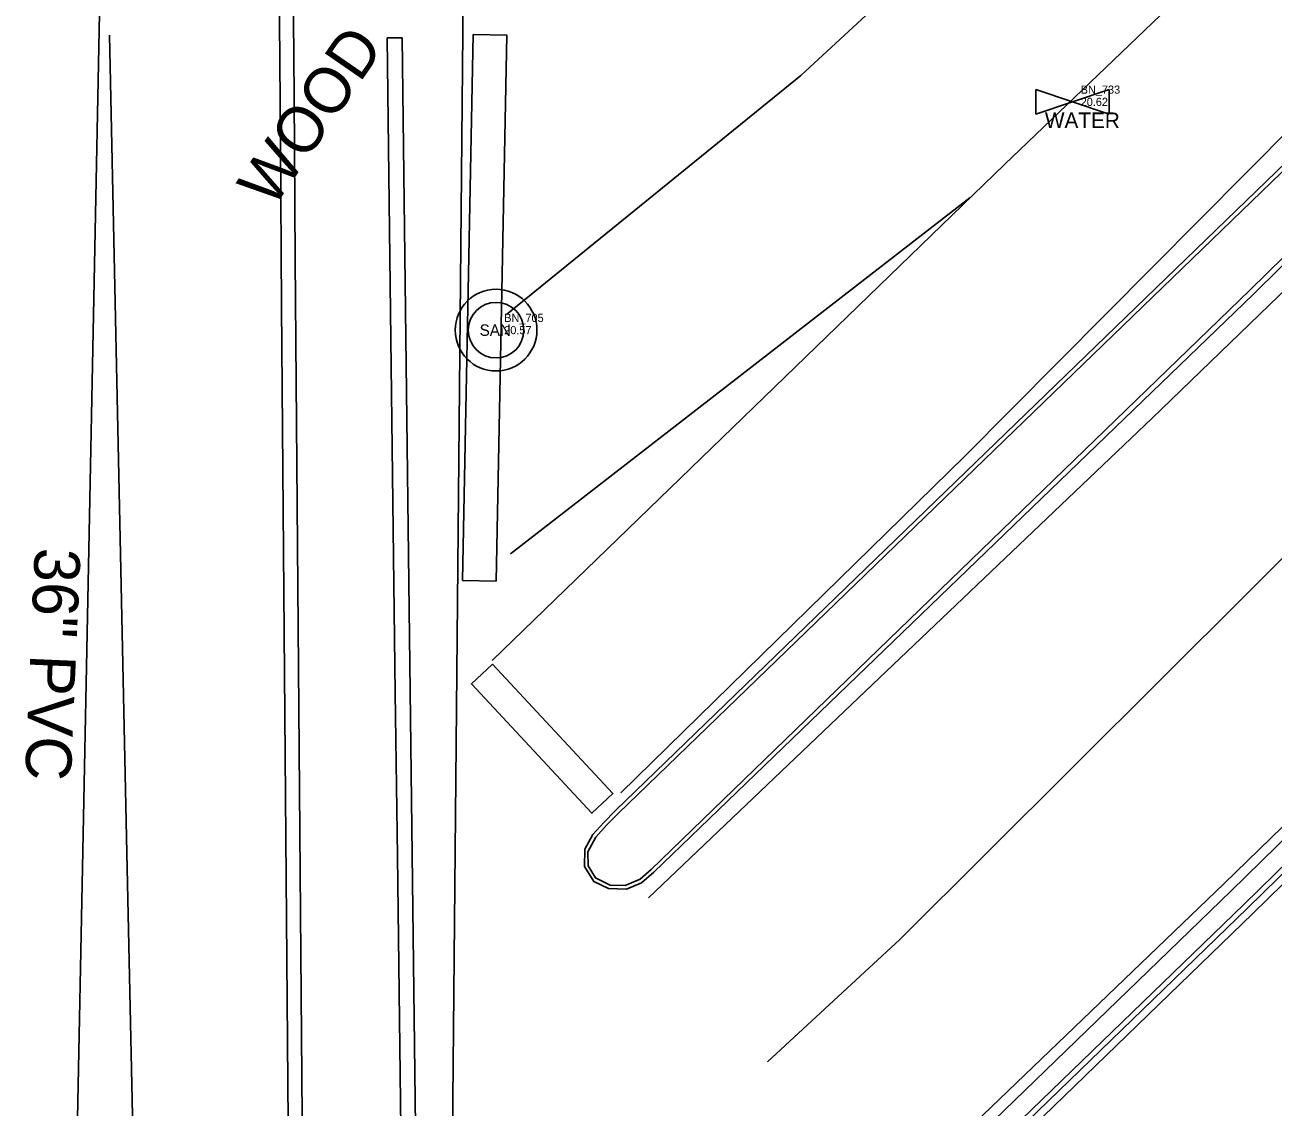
# Model space of a CAD drawing. Extents: x 509744 to 512285, y 1314862 to 1316822.
# Drawn here: x 510499.4 to 510575.8, y 1316002.7 to 1316068.9 of the extents above; entities that cross this region are included whole.
import ezdxf

# ---------------------------------------------------------------- set-up
doc = ezdxf.new("R2010")
doc.units = 0
for name, color, linetype in [('CGBack_ep', 7, 'Continuous'), ('CGep_ep', 7, 'Continuous'), ('CGFace_ep', 7, 'Continuous'), ('ElecAer_ep', 7, 'Continuous'), ('LaneLine_ep', 7, 'Continuous'), ('ManholeSS_ep', 7, 'Continuous'), ('NonPlottingEle_dp', 7, 'Continuous'), ('PavtAsphalt_ep', 7, 'Continuous'), ('PavtBreak_ep', 7, 'Continuous'), ('PipeCulvert_ep', 7, 'Continuous'), ('PMRK_ep', 7, 'Continuous'), ('TextElevLabel', 7, 'Continuous'), ('TextPtLabel', 7, 'Continuous'), ('TextTopoLabel_ep', 7, 'Continuous'), ('ValveWater_ep', 7, 'Continuous')]:
    doc.layers.add(name, color=color, linetype=linetype)

msp = doc.modelspace()

# ---------------------------------------------------------------- linework, layer by layer
at = {"layer": 'CGBack_ep'}
msp.add_lwpolyline([(510906.619, 1316389.372), (510906.094, 1316388.771), (510873.175, 1316351.137), (510840.313, 1316313.453), (510807.488, 1316275.737), (510774.647, 1316238.034), (510741.785, 1316200.35), (510708.978, 1316162.618), (510676.101, 1316124.947), (510643.265, 1316087.24), (510610.387, 1316049.569), (510574.578, 1316014.543), (510538.643, 1315979.773), (510535.201, 1315976.45), (510533.049, 1315974.36), (510531.944, 1315973.343)], dxfattribs=at)
at = {"layer": 'CGep_ep'}
msp.add_lwpolyline([(510741.133, 1316200.92), (510708.324, 1316163.19), (510675.447, 1316125.519), (510642.649, 1316087.779), (510609.794, 1316050.088), (510574.024, 1316015.104), (510538.089, 1315980.334), (510534.647, 1315977.011), (510532.5, 1315974.915), (510530.292, 1315972.882), (510528.11, 1315970.821), (510525.996, 1315968.692), (510524.588, 1315967.118), (510523.15, 1315965.736), (510520.573, 1315962.735), (510517.125, 1315957.899), (510513.652, 1315953.084), (510511.433, 1315949.796), (510511.381, 1315949.707)], dxfattribs=at)
at = {"layer": 'CGFace_ep'}
for points in [[(510906.225, 1316389.717), (510905.7, 1316389.116), (510872.806, 1316351.459), (510839.944, 1316313.775), (510807.114, 1316276.063), (510774.274, 1316238.36), (510741.428, 1316200.662), (510708.597, 1316162.951), (510675.716, 1316125.283), (510642.909, 1316087.551), (510610.035, 1316049.877), (510574.249, 1316014.876), (510538.32, 1315980.1), (510534.878, 1315976.777), (510532.728, 1315974.684), (510531.649, 1315973.653)], [(510677.624, 1316188.156), (510644.934, 1316150.33), (510614.742, 1316110.507), (510584.793, 1316068.08), (510535.702, 1316020.674), (510535.012, 1316019.968), (510534.34, 1316019.226), (510533.862, 1316018.328), (510533.88, 1316017.469), (510534.325, 1316016.717), (510535.223, 1316016.278), (510536.135, 1316016.259), (510537.052, 1316016.637), (510537.733, 1316017.235), (510574.386, 1316052.693), (510589.18, 1316067.209), (510622.024, 1316104.903), (510654.893, 1316142.579), (510687.734, 1316180.281)]]:
    msp.add_lwpolyline(points, dxfattribs=at)
at = {"layer": 'ElecAer_ep'}
msp.add_line((510526.298, 1316077.939), (510525.108, 1315952.49), dxfattribs=at)
at = {"layer": 'LaneLine_ep'}
msp.add_lwpolyline([(510897.396, 1316400.456), (510862.803, 1316359.889), (510832.807, 1316326.306), (510798.287, 1316286.158), (510735.028, 1316214.077), (510672.101, 1316140.99), (510641.285, 1316105.546), (510607.971, 1316067.456), (510579.636, 1316039.519), (510552.966, 1316012.957), (510544.856, 1316005.46)], dxfattribs=at)
at = {"layer": 'ManholeSS_ep'}
for radius in [2.5, 1.7]:
    msp.add_circle((510528.235, 1316050.255), radius, dxfattribs=at)
at = {"layer": 'PavtAsphalt_ep'}
for points in [[(510707.473, 1316163.934), (510674.596, 1316126.263), (510641.798, 1316088.523), (510608.937, 1316050.838), (510573.224, 1316015.914), (510537.289, 1315981.144)], [(510584.562, 1316068.226), (510535.54, 1316020.846), (510534.828, 1316020.117), (510534.156, 1316019.375), (510533.678, 1316018.477), (510533.647, 1316017.426), (510534.219, 1316016.506), (510535.117, 1316016.067), (510536.213, 1316016.035), (510537.131, 1316016.414), (510537.898, 1316017.066), (510574.61, 1316052.466), (510589.378, 1316067.033)]]:
    msp.add_lwpolyline(points, dxfattribs=at)
at = {"layer": 'PavtBreak_ep'}
msp.add_lwpolyline([(510504.573, 1316068.305), (510505.103, 1316043.281), (510505.632, 1316018.255), (510505.973, 1316002.185), (510505.733, 1315977.345), (510505.494, 1315952.305), (510505.384, 1315940.768)], dxfattribs=at)
at = {"layer": 'PipeCulvert_ep'}
msp.add_line((510504.215, 1316082.587), (510502.341, 1315988.248), dxfattribs=at)
at = {"layer": 'PMRK_ep'}
msp.add_line((510557.267, 1316058.377), (510529.124, 1316036.563), dxfattribs=at)
for points in [[(510535.866, 1316021.93), (510556.919, 1316042.511), (510582.825, 1316068.607), (510593.386, 1316083.059), (510607.359, 1316103.531), (510623.33, 1316125.319), (510633.496, 1316138.899), (510638.066, 1316145.628), (510647.147, 1316156.192), (510653.473, 1316163.069), (510687.498, 1316202.708), (510722.09, 1316242.444), (510755.272, 1316280.321), (510766.456, 1316293.373), (510794.192, 1316325.064), (510820.447, 1316355.021), (510853.244, 1316392.949), (510872.661, 1316415.2)], [(510884.673, 1316403.159), (510870.788, 1316387.208), (510849.585, 1316362.33), (510828.523, 1316338.554), (510820.8, 1316329.719), (510787.708, 1316291.824), (510770.573, 1316272.032), (510764.182, 1316264.659), (510754.834, 1316253.63), (510732.404, 1316228.471), (510698.276, 1316188.316), (510666.093, 1316152.025), (510645.066, 1316127.714), (510612.99, 1316091.542), (510590.511, 1316066.206), (510568.388, 1316044.854), (510537.566, 1316015.493)], [(510904.086, 1316390.528), (510871.21, 1316352.856), (510838.345, 1316315.173), (510805.495, 1316277.479), (510772.752, 1316239.691), (510739.91, 1316201.99), (510707.064, 1316164.292), (510674.247, 1316126.568), (510641.452, 1316088.825), (510608.591, 1316051.141), (510572.788, 1316016.355), (510536.711, 1315981.729), (510533.269, 1315978.406), (510531.042, 1315976.391), (510528.825, 1315974.367), (510526.652, 1315972.298), (510524.577, 1315970.129)], [(510528.875, 1316051.218), (510546.9, 1316065.844), (510574.347, 1316091.205), (510596.48, 1316115.283), (510615.946, 1316137.592), (510622.281, 1316144.577)], [(510528.002, 1316030.027), (510559.36, 1316060.405), (510573.682, 1316074.111)], [(510516.421, 1315994.578), (510516.342, 1316004.578), (510516.263, 1316014.577), (510516.183, 1316024.577), (510516.104, 1316034.577), (510516.025, 1316044.576), (510515.945, 1316054.576), (510515.866, 1316064.576), (510515.809, 1316071.728), (510514.948, 1316071.721)], [(510514.948, 1316071.721), (510515.028, 1316061.721), (510515.107, 1316051.722), (510515.186, 1316041.722), (510515.266, 1316031.722), (510515.345, 1316021.723), (510515.425, 1316011.723), (510515.504, 1316001.723)], [(510522.483, 1316068.153), (510522.606, 1316058.154), (510522.73, 1316048.155), (510522.853, 1316038.156), (510522.977, 1316028.156), (510523.1, 1316018.157), (510523.224, 1316008.158), (510523.348, 1315998.159), (510523.471, 1315988.159), (510523.595, 1315978.16), (510523.719, 1315968.072), (510522.809, 1315968.061), (510522.686, 1315978.06), (510522.562, 1315988.059), (510522.439, 1315998.059), (510522.315, 1316008.058), (510522.191, 1316018.057), (510522.068, 1316028.056), (510521.944, 1316038.056), (510521.821, 1316048.055), (510521.697, 1316058.054), (510521.573, 1316068.142), (510522.483, 1316068.153)]]:
    msp.add_lwpolyline(points, dxfattribs=at)
for points in [[(510526.832, 1316068.357), (510526.186, 1316034.929), (510528.242, 1316034.889), (510528.888, 1316068.317)], [(510528.015, 1316029.801), (510535.395, 1316021.883), (510534.105, 1316020.68), (510526.725, 1316028.598)]]:
    msp.add_lwpolyline(points, close=True, dxfattribs=at)
at = {"layer": 'ValveWater_ep'}
for p, q in [((510565.78, 1316063.479), (510561.28, 1316064.979)), ((510561.28, 1316063.479), (510565.78, 1316064.979)), ((510561.28, 1316063.479), (510561.28, 1316064.979)), ((510565.78, 1316064.979), (510565.78, 1316063.479))]:
    msp.add_line(p, q, dxfattribs=at)

# ---------------------------------------------------------------- texts
at = {"layer": 'ManholeSS_ep'}
msp.add_text('SAN', height=0.7, dxfattribs=at).set_placement((510527.227, 1316049.905))
at = {"layer": 'NonPlottingEle_dp'}
msp.add_text('36" PVC', height=2.8, rotation=267.55779, dxfattribs=at).set_placement((510500, 1316036.964))
at = {"layer": 'TextElevLabel'}
for s, p in [('20.62', (510564.03, 1316063.979)), ('20.57', (510528.735, 1316050.005))]:
    msp.add_text(s, height=0.5, dxfattribs=at).set_placement(p)
at = {"layer": 'TextPtLabel'}
for s, p in [('BN_733', (510564.03, 1316064.729)), ('BN_705', (510528.735, 1316050.755))]:
    msp.add_text(s, height=0.5, dxfattribs=at).set_placement(p)
at = {"layer": 'TextTopoLabel_ep'}
msp.add_text('WOOD', height=2.8, rotation=55.40278, dxfattribs=at).set_placement((510514.575, 1316057.647))
at = {"layer": 'ValveWater_ep'}
msp.add_text('WATER', height=0.95, dxfattribs=at).set_placement((510561.841, 1316062.629))

doc.saveas('drawing.dxf')
